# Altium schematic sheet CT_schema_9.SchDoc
size 147 x 119 mm
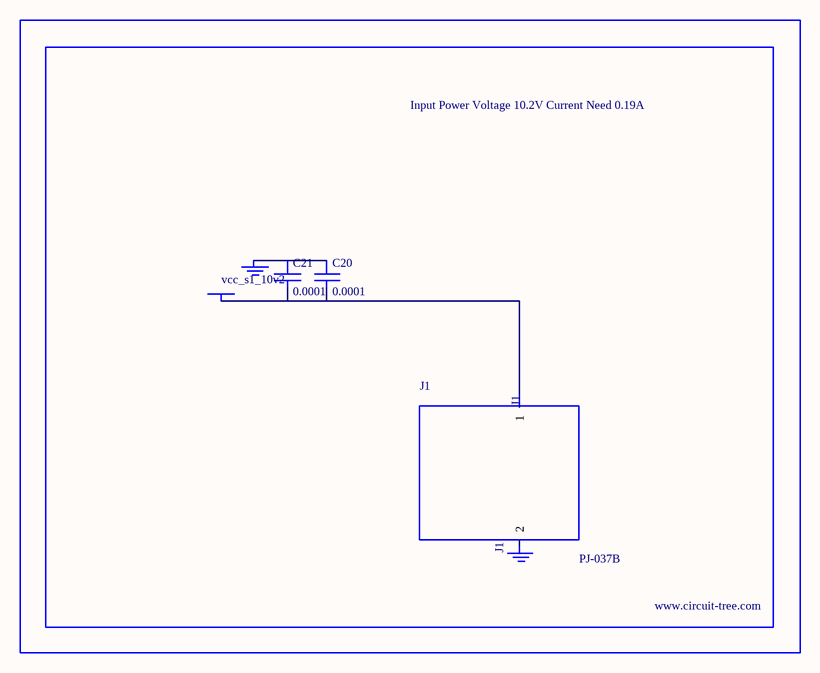
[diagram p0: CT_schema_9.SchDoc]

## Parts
BORDER8  (no value)
C20  0.0001  [EXV-9H]
C21  0.0001  [EXV-9H]
GND_INSTANCE_8_0  (no value)
GND_INSTANCE_8_1  (no value)
J1  PJ-037B  [PJ-037B_PACKAGE]
POWER_INSTANCE_8_0  vcc_s1_10v2

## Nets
NetC20_1: C20.1 C21.1 GND_INSTANCE_8_0.0(GND)
NetC20_2: C20.2 C21.2 J1.1 POWER_INSTANCE_8_0.0(PWR)

Not connected (* = marked no-connect by the designer): GND_INSTANCE_8_1 0(GND); J1 2

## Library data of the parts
BORDER8 = BORDER_PAGE8
C20 C21 = EDK107M035A9HAA
GND_INSTANCE_8_0 GND_INSTANCE_8_1 = GND
POWER_INSTANCE_8_0 = PWR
